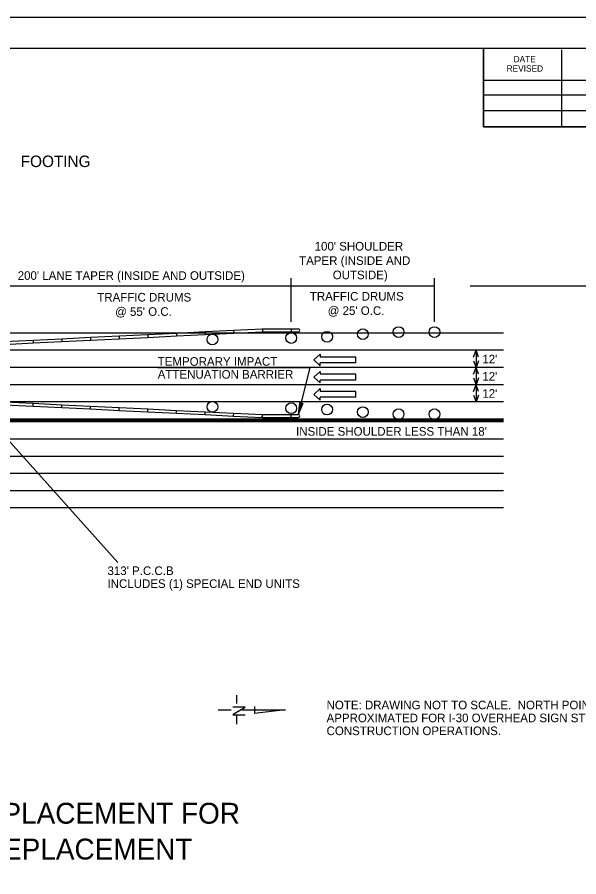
# Model space of a CAD drawing. Extents: x 1397271 to 1411271, y 376395 to 377888.
# Drawn here: x 1410252 to 1410746, y 377132 to 377888 of the extents above; entities that cross this region are included whole.
import ezdxf

# ---------------------------------------------------------------- set-up
doc = ezdxf.new("R2010")
doc.units = 0
for name, color, linetype in [('Default', 7, 'Continuous'), ('R_Border', 7, 'Continuous'), ('R_Dimension', 7, 'Continuous'), ('R_Draft', 7, 'Continuous'), ('R_Horz Alg', 7, 'Continuous'), ('R_MOT', 7, 'Continuous'), ('R_No Plot', 7, 'Continuous')]:
    doc.layers.add(name, color=color, linetype=linetype)

msp = doc.modelspace()

# ---------------------------------------------------------------- linework, layer by layer
at = {"layer": 'Default'}
for p, q in [((1410493.26, 377613.92), (1410499.56, 377613.92)), ((1410493.25, 377611.39), (1410499.56, 377611.39)), ((1410500.5, 377548.93), (1410499.56, 377538.52)), ((1410503.51, 377548.2), (1410499.56, 377538.52)), ((1410500.75, 377548.87), (1410499.97, 377540.2)), ((1410503.26, 377548.26), (1410499.97, 377540.2)), ((1410501.01, 377548.81), (1410500.39, 377541.92)), ((1410503.01, 377548.32), (1410500.39, 377541.92)), ((1410503.51, 377548.2), (1410500.5, 377548.93)), ((1410501.26, 377548.75), (1410500.79, 377543.6)), ((1410502.76, 377548.38), (1410500.79, 377543.6)), ((1410501.51, 377548.68), (1410501.21, 377545.3)), ((1410502.49, 377548.45), (1410501.21, 377545.3)), ((1410501.77, 377548.62), (1410501.62, 377546.98)), ((1410502.24, 377548.51), (1410501.62, 377546.98)), ((1410493.25, 377538.52), (1410499.56, 377538.52)), ((1410493.26, 377536), (1410499.56, 377536))]:
    msp.add_line(p, q, dxfattribs=at)
for centre, start, end in [((1410499.64, 377612.65), 265.96283, 93.80647), ((1410499.64, 377537.26), 266.19353, 94.03717)]:
    msp.add_arc(centre, 1.26, start, end, dxfattribs=at)
at = {"layer": 'R_Border'}
for p, q in [((1409024.85, 377860.72), (1411238.15, 377860.72)), ((1410662.32, 377791.56), (1410662.32, 377860.72)), ((1410731.34, 377791.56), (1410731.34, 377859.32)), ((1410662.32, 377832.58), (1410936.44, 377832.58)), ((1410662.32, 377819.56), (1410936.44, 377819.56)), ((1410662.32, 377791.56), (1410662.32, 377805.98)), ((1410662.32, 377805.98), (1410936.44, 377805.98)), ((1411238.15, 377791.56), (1410662.32, 377791.56))]:
    msp.add_line(p, q, dxfattribs=at)
at = {"layer": 'R_Dimension'}
for p, q in [((1410241.2, 377651.67), (1410619.31, 377651.67)), ((1410493.22, 377620), (1410493.22, 377658.53)), ((1410619.31, 377620), (1410619.31, 377658.53)), ((1410650.61, 377651.67), (1410838.88, 377651.67)), ((1410653.75, 377589.11), (1410655.89, 377595.04)), ((1410655.89, 377595.04), (1410655.89, 377549.65)), ((1410658.06, 377589.12), (1410655.89, 377595.04)), ((1410653.73, 377585.83), (1410655.89, 377579.91)), ((1410658.04, 377585.84), (1410655.89, 377579.91)), ((1410653.75, 377573.98), (1410655.89, 377579.91)), ((1410658.06, 377573.99), (1410655.89, 377579.91)), ((1410653.73, 377570.69), (1410655.89, 377564.78)), ((1410658.04, 377570.7), (1410655.89, 377564.78)), ((1410653.75, 377558.85), (1410655.89, 377564.78)), ((1410658.06, 377558.86), (1410655.89, 377564.78)), ((1410653.73, 377555.56), (1410655.89, 377549.65)), ((1410658.04, 377555.57), (1410655.89, 377549.65)), ((1410341.02, 377408.39), (1410243.75, 377516.9))]:
    msp.add_line(p, q, dxfattribs=at)
msp.add_lwpolyline([(1410375.88, 377579.89), (1410509.65, 377579.91), (1410499.56, 377538.52)], dxfattribs=at)
at = {"layer": 'R_Draft'}
for p, q in [((1410445.27, 377291.68), (1410445.27, 377284.35)), ((1410461.03, 377281.65), (1410461.03, 377275.51)), ((1410429.09, 377278.97), (1410440.46, 377278.97)), ((1410445.27, 377274.09), (1410445.27, 377266.26)), ((1410449.82, 377278.97), (1410488.47, 377278.97)), ((1410488.47, 377278.97), (1410460.83, 377275.51))]:
    msp.add_line(p, q, dxfattribs=at)
at = {"layer": 'R_Horz Alg'}
for p, q in [((1410679.99, 377610.21), (1409657.93, 377610.21)), ((1410679.99, 377595.07), (1409657.93, 377595.07)), ((1410679.99, 377579.94), (1409657.93, 377579.94)), ((1410679.99, 377564.81), (1409657.93, 377564.81)), ((1410679.99, 377549.68), (1409657.93, 377549.68)), ((1410679.99, 377533.29), (1409657.93, 377533.29)), ((1410266.45, 377534.55), (1409991.58, 377534.55)), ((1410266.45, 377532.03), (1409991.58, 377532.03)), ((1410679.99, 377534.55), (1410266.45, 377534.55)), ((1410679.99, 377532.03), (1410266.45, 377532.03)), ((1410679.99, 377516.9), (1409657.93, 377516.9)), ((1410679.99, 377501.77), (1409657.93, 377501.77)), ((1410679.99, 377486.64), (1409657.93, 377486.64)), ((1410679.99, 377471.51), (1409657.93, 377471.51)), ((1410679.99, 377456.38), (1409657.93, 377456.38))]:
    msp.add_line(p, q, dxfattribs=at)
at = {"layer": 'R_MOT'}
for p, q in [((1410442.72, 377612.67), (1410467.91, 377613.91)), ((1410467.91, 377613.91), (1410468.03, 377611.39)), ((1410468.03, 377613.92), (1410493.25, 377613.92)), ((1410468.03, 377613.92), (1410468.03, 377611.39)), ((1410493.25, 377613.92), (1410493.25, 377611.39)), ((1410291.6, 377605.23), (1410316.79, 377606.47)), ((1410316.79, 377606.47), (1410341.98, 377607.71)), ((1410316.79, 377606.47), (1410316.91, 377603.95)), ((1410316.79, 377606.47), (1410316.91, 377603.95)), ((1410341.98, 377607.71), (1410367.16, 377608.95)), ((1410341.98, 377607.71), (1410342.1, 377605.19)), ((1410341.98, 377607.71), (1410342.1, 377605.19)), ((1410342.1, 377605.19), (1410367.29, 377606.43)), ((1410367.16, 377608.95), (1410392.35, 377610.19)), ((1410367.16, 377608.95), (1410367.29, 377606.43)), ((1410367.16, 377608.95), (1410367.29, 377606.43)), ((1410367.29, 377606.43), (1410392.47, 377607.67)), ((1410392.35, 377610.19), (1410417.54, 377611.43)), ((1410392.35, 377610.19), (1410392.47, 377607.67)), ((1410392.35, 377610.19), (1410392.47, 377607.67)), ((1410392.47, 377607.67), (1410417.66, 377608.91)), ((1410417.54, 377611.43), (1410442.72, 377612.67)), ((1410417.54, 377611.43), (1410417.66, 377608.91)), ((1410417.54, 377611.43), (1410417.66, 377608.91)), ((1410417.66, 377608.91), (1410442.85, 377610.15)), ((1410442.72, 377612.67), (1410442.85, 377610.15)), ((1410442.72, 377612.67), (1410442.85, 377610.15)), ((1410442.85, 377610.15), (1410468.03, 377611.39)), ((1410468.03, 377611.39), (1410493.25, 377611.39)), ((1410241.23, 377602.75), (1410266.42, 377603.99)), ((1410241.35, 377600.23), (1410266.54, 377601.47)), ((1410266.42, 377603.99), (1410291.6, 377605.23)), ((1410266.42, 377603.99), (1410266.54, 377601.47)), ((1410266.42, 377603.99), (1410266.54, 377601.47)), ((1410266.54, 377601.47), (1410291.73, 377602.71)), ((1410291.6, 377605.23), (1410291.73, 377602.71)), ((1410291.6, 377605.23), (1410291.73, 377602.71)), ((1410291.73, 377602.71), (1410316.91, 377603.95)), ((1410316.91, 377603.95), (1410342.1, 377605.19)), ((1410513.28, 377586.57), (1410518.81, 377591.61)), ((1410518.81, 377591.61), (1410518.81, 377589.09)), ((1410518.81, 377581.52), (1410513.28, 377586.57)), ((1410550.31, 377589.09), (1410518.81, 377589.09)), ((1410550.31, 377584.04), (1410518.81, 377584.04)), ((1410518.81, 377581.52), (1410518.81, 377584.04)), ((1410550.31, 377584.04), (1410550.31, 377589.09)), ((1410513.28, 377571.44), (1410518.81, 377576.48)), ((1410518.81, 377576.48), (1410518.81, 377573.96)), ((1410518.81, 377566.39), (1410513.28, 377571.44)), ((1410550.31, 377573.96), (1410518.81, 377573.96)), ((1410550.31, 377568.91), (1410518.81, 377568.91)), ((1410518.81, 377566.39), (1410518.81, 377568.91)), ((1410550.31, 377568.91), (1410550.31, 377573.96)), ((1410513.28, 377556.31), (1410518.81, 377561.35)), ((1410518.81, 377561.35), (1410518.81, 377558.83)), ((1410518.81, 377551.26), (1410513.28, 377556.31)), ((1410550.31, 377558.83), (1410518.81, 377558.83)), ((1410550.31, 377553.78), (1410518.81, 377553.78)), ((1410518.81, 377551.26), (1410518.81, 377553.78)), ((1410550.31, 377553.78), (1410550.31, 377558.83)), ((1410241.23, 377547.16), (1410266.42, 377545.92)), ((1410241.35, 377549.68), (1410266.54, 377548.44)), ((1410266.42, 377545.92), (1410266.54, 377548.44)), ((1410266.42, 377545.92), (1410266.54, 377548.44)), ((1410266.42, 377545.92), (1410291.6, 377544.68)), ((1410266.54, 377548.44), (1410291.73, 377547.2)), ((1410291.6, 377544.68), (1410291.73, 377547.2)), ((1410291.6, 377544.68), (1410291.73, 377547.2)), ((1410291.73, 377547.2), (1410316.91, 377545.96)), ((1410316.79, 377543.44), (1410316.91, 377545.96)), ((1410316.79, 377543.44), (1410316.91, 377545.96)), ((1410316.91, 377545.96), (1410342.1, 377544.72)), ((1410291.6, 377544.68), (1410316.79, 377543.44)), ((1410316.79, 377543.44), (1410341.98, 377542.2)), ((1410341.98, 377542.2), (1410342.1, 377544.72)), ((1410341.98, 377542.2), (1410342.1, 377544.72)), ((1410341.98, 377542.2), (1410367.16, 377540.96)), ((1410342.1, 377544.72), (1410367.29, 377543.48)), ((1410367.16, 377540.96), (1410367.29, 377543.48)), ((1410367.16, 377540.96), (1410367.29, 377543.48)), ((1410367.16, 377540.96), (1410392.35, 377539.72)), ((1410367.29, 377543.48), (1410392.47, 377542.24)), ((1410392.35, 377539.72), (1410392.47, 377542.24)), ((1410392.35, 377539.72), (1410392.47, 377542.24)), ((1410392.35, 377539.72), (1410417.54, 377538.48)), ((1410392.47, 377542.24), (1410417.66, 377541)), ((1410417.54, 377538.48), (1410417.66, 377541)), ((1410417.54, 377538.48), (1410417.66, 377541)), ((1410417.54, 377538.48), (1410442.72, 377537.24)), ((1410417.66, 377541), (1410442.85, 377539.76)), ((1410442.72, 377537.24), (1410442.85, 377539.76)), ((1410442.72, 377537.24), (1410442.85, 377539.76)), ((1410442.85, 377539.76), (1410468.03, 377538.52)), ((1410467.91, 377536), (1410468.03, 377538.52)), ((1410468.03, 377538.52), (1410493.25, 377538.52)), ((1410468.03, 377536), (1410468.03, 377538.52)), ((1410493.25, 377536), (1410493.25, 377538.52)), ((1410442.72, 377537.24), (1410467.91, 377536)), ((1410468.03, 377536), (1410493.25, 377536))]:
    msp.add_line(p, q, dxfattribs=at)
for centre in [(1410556.32, 377609.21), (1410587.78, 377611.09), (1410619.31, 377611.09), (1410424.04, 377604.59), (1410493.38, 377605.86), (1410524.88, 377606.96), (1410424.04, 377545.32), (1410493.38, 377544.05), (1410524.88, 377542.95), (1410556.32, 377540.7), (1410587.78, 377538.82), (1410619.31, 377538.82)]:
    msp.add_circle(centre, 4.73, dxfattribs=at)
at = {"layer": 'R_No Plot'}
msp.add_line((1408938.04, 377887.98), (1411271.41, 377887.98), dxfattribs=at)
for points in [[(1408937.99, 377887.98), (1411271.41, 377887.98), (1411271.41, 376394.59), (1408937.99, 376394.59)], [(1410662.32, 377860.72), (1410662.32, 377791.56), (1410912.44, 377791.56), (1410912.44, 377771.12), (1411074.84, 377771.12), (1411074.84, 377600.79), (1411238.15, 377600.79), (1411238.15, 376422.47), (1409024.85, 376422.47), (1409024.85, 377860.72)]]:
    msp.add_lwpolyline(points, close=True, dxfattribs=at)

# ---------------------------------------------------------------- texts
at = {"layer": 'Default'}
for s, height, p in [('FOOTING', 10.087, (1410255.46, 377756.18)), ('PRECAST CONCRETE BARRIER WALL PLACEMENT FOR', 18.3753, (1409782.03, 377178.71)), ('OVERHEAD SIGN STRUCTURE REPLACEMENT', 18.3753, (1409852.2, 377147.21))]:
    msp.add_text(s, height=height, dxfattribs=at).set_placement(p)
at = {"layer": 'R_Border'}
for s, height, p in [('DATE', 5.474, (1410688.92, 377848.4)), ('REVISED', 5.474, (1410682.76, 377840.14)), ('TEMPORARY IMPACT', 7.5652, (1410375.97, 377581.44)), ('ATTENUATION BARRIER', 7.5652, (1410375.97, 377570.09)), ("313' P.C.C.B", 7.5652, (1410331.78, 377397.42)), ('INCLUDES (1) SPECIAL END UNITS', 7.5652, (1410331.78, 377386.07)), ('NOTE: DRAWING NOT TO SCALE.  NORTH POINT ORIENTATION ', 7.5652, (1410524.44, 377279.32)), ('APPROXIMATED FOR I-30 OVERHEAD SIGN STRUCTURE ', 7.5652, (1410524.44, 377267.97)), ('CONSTRUCTION OPERATIONS.  ', 7.5652, (1410524.44, 377256.62))]:
    msp.add_text(s, height=height, dxfattribs=at).set_placement(p)
at = {"layer": 'R_Dimension'}
for s, height, p in [("100' SHOULDER", 7.5652, (1410513.93, 377682.77)), ('TAPER (INSIDE AND ', 7.5652, (1410500.29, 377670.16)), ("200' LANE TAPER (INSIDE AND OUTSIDE)", 7.5652, (1410252.81, 377656.99)), ('OUTSIDE)', 7.565, (1410529.87, 377657.55)), ('TRAFFIC DRUMS ', 7.5652, (1410322.77, 377637.95)), ('TRAFFIC DRUMS ', 7.5652, (1410509.73, 377638.76)), ("@ 55' O.C.", 7.565, (1410338.5, 377625.34)), ("@ 25' O.C.", 7.565, (1410525.45, 377626.15)), ("12'", 7.565, (1410661.42, 377583.55)), ("12'", 7.565, (1410661.42, 377568.42)), ("12'", 7.565, (1410661.42, 377553.29)), ("INSIDE SHOULDER LESS THAN 18'", 7.5652, (1410497.62, 377519.93))]:
    msp.add_text(s, height=height, dxfattribs=at).set_placement(p)
at = {"layer": 'R_Draft'}
msp.add_text('N', height=11.05, rotation=270, dxfattribs=at).set_placement((1410441.86, 377283.16))

doc.saveas('drawing.dxf')
